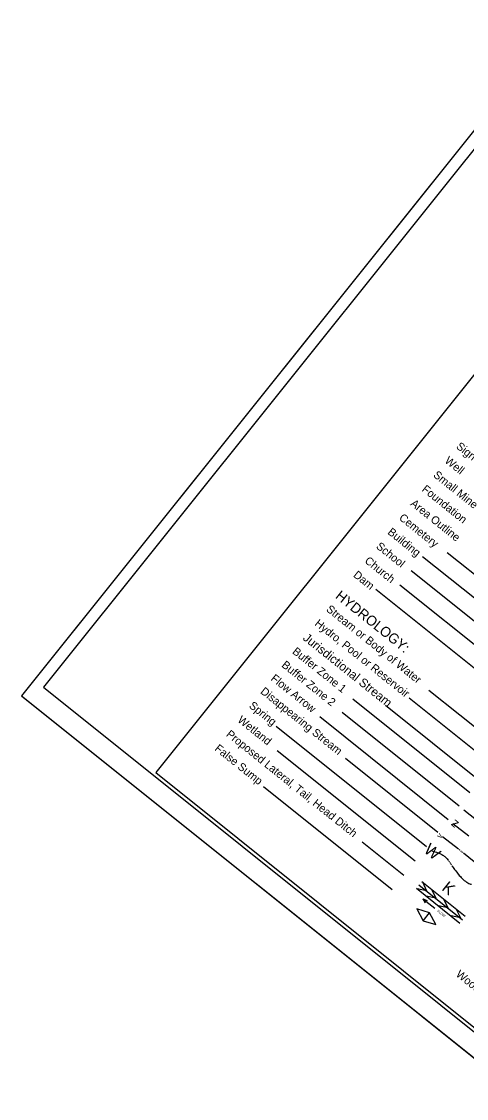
# Model space of a CAD drawing. Extents: x 1730256 to 1738218, y 910410 to 917906.
# Drawn here: x 1730904 to 1731877, y 912757 to 915111 of the extents above; entities that cross this region are included whole.
import ezdxf

# ---------------------------------------------------------------- set-up
doc = ezdxf.new("R2010")
doc.units = 0
for name, color, linetype in [('Sheet Cutting Line CELL', 7, 'Continuous'), ('Sheet Plot Border Inside CELL', 7, 'Continuous'), ('Sheet Plot Border Outside CELL', 7, 'Continuous'), ('Sheet Symbology CELL', 7, 'Continuous')]:
    doc.layers.add(name, color=color, linetype=linetype)

msp = doc.modelspace()

# ---------------------------------------------------------------- linework, layer by layer
at = {"layer": 'Sheet Cutting Line CELL'}
for p, q in [((1732278.3, 915354.9), (1730903.7, 913637.3)), ((1730903.7, 913637.3), (1733533.3, 911532.8))]:
    msp.add_line(p, q, dxfattribs=at)
at = {"layer": 'Sheet Plot Border Inside CELL'}
msp.add_lwpolyline([(1730952, 913656.1), (1733554.3, 911573.5), (1734872.8, 913221.1), (1732270.6, 915303.6)], close=True, dxfattribs=at)
at = {"layer": 'Sheet Plot Border Outside CELL'}
msp.add_lwpolyline([(1730903.7, 913637.3), (1733533.3, 911532.8), (1734907.9, 913250.5), (1732278.3, 915354.9)], close=True, dxfattribs=at)
at = {"layer": 'Sheet Symbology CELL'}
for p, q in [((1732105.2, 913681.8), (1731780.8, 913941.4)), ((1732130.1, 913713.1), (1731834.4, 913949.8)), ((1732080.2, 913650.6), (1731755.8, 913910.2)), ((1732030.2, 913588.1), (1731678.2, 913869.8)), ((1732055.2, 913619.4), (1731730.8, 913878.9)), ((1731958.1, 913517.7), (1731794.1, 913648.9)), ((1731884.1, 913425.3), (1731628.4, 913629.9)), ((1731904.9, 913451.2), (1731699.4, 913615.7)), ((1731933.1, 913486.5), (1731751.4, 913631.9)), ((1731836.9, 913366.3), (1731556.1, 913591.1)), ((1731860.5, 913395.8), (1731604.8, 913600.4)), ((1731789.3, 913306.8), (1731460.7, 913569.8)), ((1731764.3, 913275.6), (1731462.6, 913517)), ((1731814.3, 913338), (1731612.1, 913499.9)), ((1731714.3, 913213.1), (1731432.8, 913438.4)), ((1731871.1, 913388.2), (1731922.3, 913347.2)), ((1731847.1, 913358.2), (1731881.5, 913330.7)), ((1731824.5, 913329.9), (1731858.9, 913302.4)), ((1731739.3, 913244.4), (1731648.5, 913317.1)), ((1731860.4, 913301.1), (1731862, 913299.9)), ((1731863.6, 913298.6), (1731865.1, 913297.4)), ((1731866.7, 913296.1), (1731868.2, 913294.9)), ((1731869.8, 913293.6), (1731916.6, 913256.1)), ((1731842.5, 913269.2), (1731843.6, 913267.5)), ((1731767, 913216.6), (1731862.3, 913140.3)), ((1731789.5, 913210.5), (1731768.8, 913215.1)), ((1731772.4, 913224.2), (1731868.1, 913147.6)), ((1731778.8, 913231.3), (1731874.1, 913155.1)), ((1731780.2, 913230.2), (1731789.5, 913210.5)), ((1731800.1, 913214.3), (1731809.4, 913194.6)), ((1731781.3, 913193.6), (1731807.3, 913172.8)), ((1731781.3, 913193.6), (1731790.5, 913189.7)), ((1731781.3, 913193.6), (1731786.4, 913184.6)), ((1731809.4, 913194.6), (1731788.8, 913199.2)), ((1731826.5, 913193.1), (1731835.9, 913173.4)), ((1731795.6, 913162.5), (1731767.8, 913171.2)), ((1731767.8, 913171.2), (1731781.8, 913145.2)), ((1731835.9, 913173.4), (1731815.3, 913177.9)), ((1731854.2, 913171), (1731863.2, 913151.5)), ((1731781.8, 913145.2), (1731795.6, 913162.5)), ((1731781.8, 913145.2), (1731809.5, 913137.2)), ((1731809.5, 913137.2), (1731795.6, 913162.5)), ((1731863.2, 913151.5), (1731842.8, 913155.9))]:
    msp.add_line(p, q, dxfattribs=at)
msp.add_lwpolyline([(1734850.1, 913232.7), (1732507.9, 915107.2), (1731197, 913469.2), (1733539.2, 911594.7)], close=True, dxfattribs=at)
for points in [[(1731799.5, 913298.7), (1731805.4, 913297), (1731811.4, 913295.3), (1731812.8, 913294.8), (1731815.3, 913293.9), (1731817.2, 913293.1), (1731819.9, 913291.8), (1731822.5, 913290.4), (1731824.6, 913289.1), (1731826.5, 913287.8), (1731828, 913286.7), (1731829.3, 913285.6), (1731831.5, 913283.6), (1731833.1, 913282), (1731834.3, 913280.8), (1731835.9, 913278.9), (1731837, 913277.5)], [(1731838.2, 913275.9), (1731838.7, 913275.1), (1731839.3, 913274.3)], [(1731840.4, 913272.6), (1731840.9, 913271.9), (1731841.5, 913270.9)], [(1731844.7, 913265.8), (1731845.6, 913264.5), (1731847.2, 913262.1), (1731850.5, 913257.6), (1731853.1, 913254.3), (1731856.9, 913249.4), (1731860.9, 913244.6), (1731863.2, 913242), (1731865.2, 913239.7), (1731867.1, 913237.8), (1731868.8, 913236.2), (1731870.3, 913234.9), (1731871.7, 913233.7), (1731874.2, 913231.8), (1731876.1, 913230.5), (1731877.6, 913229.6), (1731879.8, 913228.2), (1731882.1, 913227.1), (1731884, 913226.3), (1731885.6, 913225.6), (1731887.3, 913225.1)]]:
    msp.add_lwpolyline(points, dxfattribs=at)

# ---------------------------------------------------------------- texts
for s, height, rotation, p in [('Sign', 17.5, 321.3297, (1731852.6, 914179.8)), ('Well', 17.5, 321.3297, (1731827.6, 914148.5)), ('Small Mine', 17.5, 321.3297, (1731802.6, 914117.3)), ('Foundation', 17.5, 321.3297, (1731777.6, 914086.1)), ('Area Outline', 17.5, 321.3297, (1731752.6, 914054.8)), ('Cemetery', 17.5, 321.3297, (1731727.6, 914023.6)), ('Building', 17.5, 321.3297, (1731702.7, 913992.4)), ('School', 17.5, 321.3297, (1731677.6, 913961.2)), ('Church', 17.5, 321.3297, (1731652.5, 913929.6)), ('Dam', 17.5, 321.3297, (1731627.7, 913898.7)), ('HYDROLOGY:', 22, 321.3297, (1731588.3, 913852.2)), ('Stream or Body of Water', 17.5, 321.3297, (1731568.4, 913823.8)), ('Hydro, Pool or Reservoir', 17.5, 321.3297, (1731543.4, 913792.6)), ('Jurisdictional Stream', 19.292, 321.3297, (1731517.3, 913760.9)), ('Buffer Zone 1', 17.5, 321.3297, (1731494.4, 913731.3)), ('Buffer Zone 2', 17.5, 321.3297, (1731470.9, 913701.9)), ('Flow Arrow', 17.5, 321.3297, (1731447.3, 913672.4)), ('Disappearing Stream', 17.5, 321.3297, (1731424.6, 913644.1)), ('Spring', 17.5, 321.3297, (1731399.6, 913612.9)), ('Wetland', 17.5, 321.3297, (1731374.6, 913581.6)), ('Proposed Lateral, Tail, Head Ditch', 17.5, 321.3297, (1731349.7, 913550.4)), ('False Sump', 17.5, 321.3297, (1731324.7, 913519.2)), ('z', 20, 141.3297, (1731861.2, 913359.7)), ('v', 13.2, 51.0888, (1731819.8, 913324.1)), ('W', 25.5, 321.3297, (1731781.6, 913296.7)), ('K', 25.5, 321.3297, (1731821, 913213.9)), ('FLOW', 5.19, 321.3297, (1731811.8, 913165.8)), ('Woods Line', 17.5, 321.3297, (1731852, 913025.6))]:
    msp.add_text(s, height=height, rotation=rotation, dxfattribs=at).set_placement(p)

doc.saveas('drawing.dxf')
